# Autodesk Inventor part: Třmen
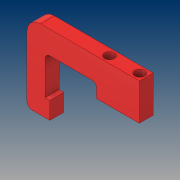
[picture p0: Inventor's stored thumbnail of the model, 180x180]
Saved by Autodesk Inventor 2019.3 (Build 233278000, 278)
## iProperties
Created: 2019-03
Part Number: Třmen
Material: Ocel, litá
Document SubType Name: Modeling
Designer: B-hon
Density: 7.85 g/cm^3
Appearance: Světle červená
Mass: 673.194 g
Surface Area: 212.934 cm^2
Volume: 85.7572 cm^3
Author: B-hon
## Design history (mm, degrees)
sketch "Náčrt1"
  geometry: L1 (0, 0)-(-5, 0); L2 (-5, 0)-(-5, -20); L3 (-5, -20)-(0, -20); L4 (0, -20)-(0, 0); L5 (36, 0)-(41, 0); L6 (41, 0)-(41, -20); L7 (41, -20)-(36, -20); L8 (36, -20)-(36, 0); L9 (-5, -1)-(-10, -1); L10 (-10, -1)-(-10, 41); L11 (-10, 41)-(46, 41); L12 (46, 41)-(46, -1); L13 (46, -1)-(41, -1); L14 (41, -1)-(41, -20); L15 (41, -20)-(71, -20); L16 (76, 10)-(76, 66); L17 (76, 66)-(-30, 66); L18 (-30, 66)-(-30, -20); L19 (-30, -20)-(-5, -20); L20 (-5, -20)-(-5, -1); L21 (71, -20)-(121, -20); L22 (121, -20)-(121, 10); L23 (121, 10)-(76, 10)
  constraints: 46 end point, 12 perpendicular, 5 horizontal, 5 parallel, 5 point on line, 1 horizontal alignment
  dimensions: "d0" = 5 distance of L3.end L2.end; "d1" = 5 distance of L6.end L7.end; "d2" = 36 distance between parallel lines of L8 L4; "d3" = 19 distance of L14.end L13.end; "d4" = 19 distance from line of L19 L9.start; "d5" = 1 distance between parallel lines of L13 L5; "d6" = 20 distance of L3.end L1.start; "d7" = 42 distance of L9.end L10.end; "d8" = 5 distance of L9.start L9.end; "d9" = 5 distance of L12.end L13.end; "d10" = 20 distance between parallel lines of L10 L18; "d11" = 30 distance between parallel lines of L16 L12; "d12" = 25 distance between parallel lines of L11 L17; "d20" = 45 distance of L16.start L22.end; "d21" = 30 distance of L22.end L21.end
extrude "Vysunutí2" new body sketch "Náčrt1" distance "d22" = 15; taper "d23" = 0 deg
fillet "Zaoblení5" dims "d25" = 6
fillet "Zaoblení6" dims "d26" = 5
node "Upravit přímo1"
sketch "Náčrt2"
  geometry: L1 (29.332, 26)-(132.747, 26); L2 (132.747, 26)-(132.747, -46.725); L3 (132.747, -46.725)-(29.332, -46.725); L4 (29.332, -46.725)-(29.332, 26); L5 (76, 66)-(-30, 66) reference; 3 further points
  constraints: 8 end point, 2 parallel, 1 horizontal, 1 perpendicular
  dimensions: "d30" = 40 distance between parallel lines of L1 L5
extrude "Vysunutí3" cut sketch "Náčrt2" distance "d31" = 20; taper "d32" = 0 deg
node "Upravit přímo2"
fillet "Zaoblení7" dims "d36" = 15
sketch "Náčrt3"
  geometry: L1 (0, 0)-(-107.5, 0) reference; L2 (0, 15)-(0, 0) reference; 3 further points
  constraints: 1 horizontal alignment
  dimensions: "d37" = 7.5 distance from line of L1 point (-40, 7.5); "d38" = 7 distance from line of L2 point (-7, 7.5); "d39" = 33 distance of point (-7, 7.5) point (-40, 7.5)
hole "Díra1" sketch "Náčrt3" at (-7, 7.5), (-40, 7.5) diameter "d40" = 6.5; stored, may be unused: countersink angle "d44" = 90 deg, drill point angle "d46" = 118 deg; dims "d41" = 12, "d42" = 11, "d43" = 8, "d45" = 17.1
node "Těleso2"
feature "Posunout1" dims "d29" = 19
feature "Posunout2" dims "d35" = 16.5
other parameters: "sa_0" = 0, "sa_1" = -700000, "sa_2" = 0, "d27" = 0, "d28" = 0, "d33" = 0, "d34" = 0
